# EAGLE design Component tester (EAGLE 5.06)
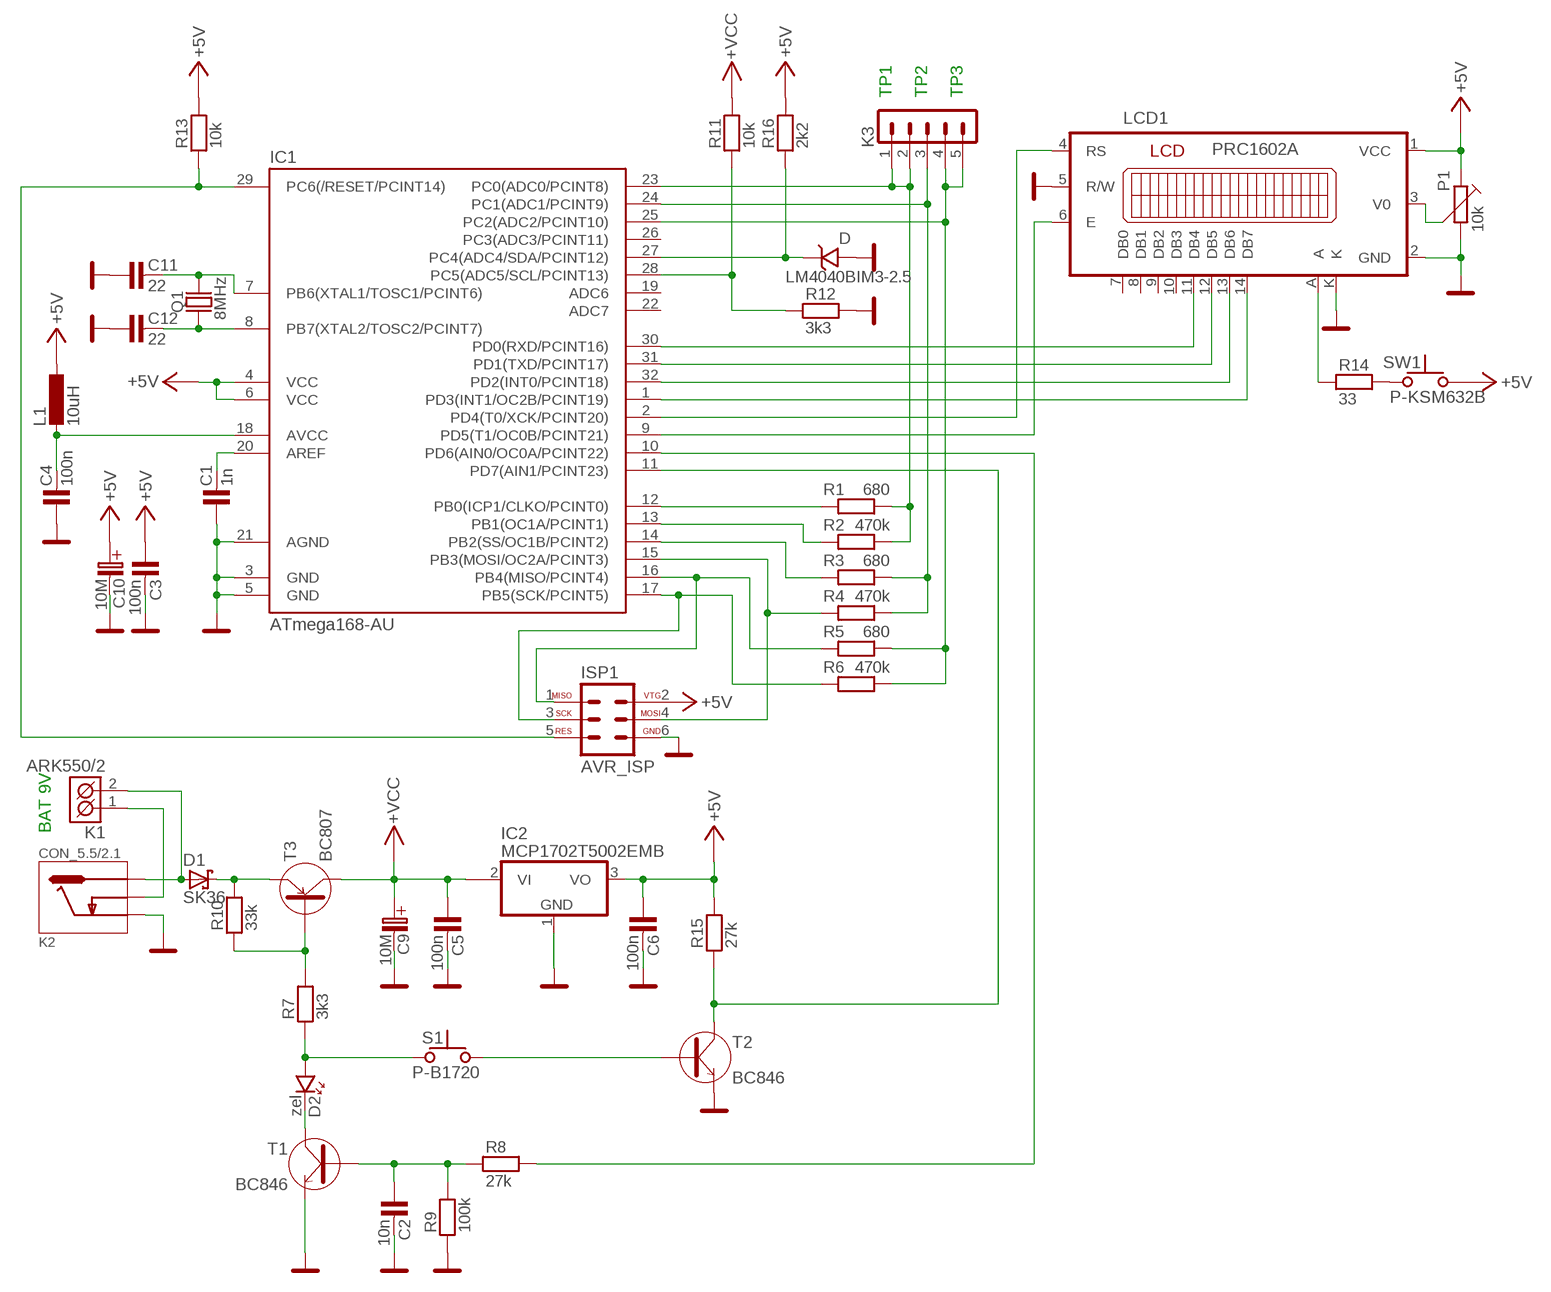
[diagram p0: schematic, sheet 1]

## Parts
C1  1n  C-KERAMIK_SMD_1206  [1206]
C2  10n  C-KERAMIK_SMD_1206  [1206]
C3  100n  C-KERAMIK_SMD_1206  [1206]
C4  100n  C-KERAMIK_SMD_1206  [1206]
C5  100n  C-KERAMIK_SMD_1206  [1206]
C6  100n  C-KERAMIK_SMD_1206  [1206]
C9  10M  10M/35V_SMD  [C_EL-SMD_C]
C10  10M  10M/35V_SMD  [C_EL-SMD_C]
C11  22  C-KERAMIK_SMD_1206  [1206]
C12  22  C-KERAMIK_SMD_1206  [1206]
D  LM4040BIM3-2.5  LM4040_SOT23  [SOT-23]
D1  SK36  SCHOTTKY-DIODESMC  [SMC]
D2  zel  LED_5  [LED_5]
IC1  ATmega168-AU  ATMEGA48/88/168-AU  [TQFP32-08]
IC2  MCP1702T5002EMB  MCP170312MB  [SOT89]
ISP1  AVR_ISP  [MLW06G]
K1  ARK550/2  [ARK550/2]
K2  CON_5.5/2.1  CON_PWR_5.5/2.1  [CON_PWR_5.5/2.1]
K3  PSH02-05P  [PSH02-05P]
L1  10uH  L-EU0207/10  [0207/10]
LCD1  PRC1602A  [PRC1602A]
P1  10k  TRIMRPT6V  [PT6V]
Q1  8MHz  XTAL_HC-49U  [HC-49U]
R1  680  R_SMD_1206  [1206]
R2  470k  R_SMD_1206  [1206]
R3  680  R_SMD_1206  [1206]
R4  470k  R_SMD_1206  [1206]
R5  680  R_SMD_1206  [1206]
R6  470k  R_SMD_1206  [1206]
R7  3k3  R_SMD_1206  [1206]
R8  27k  R_SMD_1206  [1206]
R9  100k  R_SMD_1206  [1206]
R10  33k  R_SMD_1206  [1206]
R11  10k  R_SMD_1206  [1206]
R12  3k3  R_SMD_1206  [1206]
R13  10k  R_7,5  [R-7,5]
R14  33  R_SMD_1206  [1206]
R15  27k  R_SMD_1206  [1206]
R16  2k2  R_SMD_1206  [1206]
S1  P-B1720  [P-B1720]
SW1  P-KSM632B  [P-KSM632B]
T1  BC846  [SOT-23]
T2  BC846  [SOT-23]
T3  BC807  [SOT-23]

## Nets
+5V: C3.1 C6.1 C10.+(C_EL+) IC1.4(VCC) IC1.6(VCC) IC2.3(VO) ISP1.2 L1.1 LCD1.1(VCC) P1.1 R13.2 R15.2 R16.2 SW1.1
GND: C1.1 C2.2 C3.2 C4.1 C5.2 C6.2 C9.-(C_EL-) C10.-(C_EL-) C11.1 C12.1 D.2(A) IC1.3(GND) IC1.5(GND) IC1.21(AGND) IC2.1(GND) ISP1.6 K2.3 LCD1.2(GND) LCD1.5(R/W) LCD1.K P1.2 R9.1 R12.2 T1.2(E) T2.2(E)
N$1: IC1.30(PD0(RXD/PCINT16)) LCD1.11(DB4)
N$2: IC1.31(PD1(TXD/PCINT17)) LCD1.12(DB5)
N$3: IC1.32(PD2(INT0/PCINT18)) LCD1.13(DB6)
N$4: IC1.1(PD3(INT1/OC2B/PCINT19)) LCD1.14(DB7)
N$5: IC1.9(PD5(T1/OC0B/PCINT21)) LCD1.6(E)
N$6: LCD1.3(V0) P1.3
N$7: LCD1.A R14.1
N$8: IC1.2(PD4(T0/XCK/PCINT20)) LCD1.4(RS)
N$9: IC1.16(PB4(MISO/PCINT4)) ISP1.1 R5.1
N$10: IC1.17(PB5(SCK/PCINT5)) ISP1.3 R6.1
N$11: R14.2 SW1.2
N$12: D1.C R10.2 T3.2(E)
N$13: D.1(K) IC1.27(PC4(ADC4/SDA/PCINT12)) R16.1
N$14: IC1.28(PC5(ADC5/SCL/PCINT13)) R11.1 R12.1
N$15: C12.2 IC1.8(PB7(XTAL2/TOSC2/PCINT7)) Q1.1
N$16: C11.2 IC1.7(PB6(XTAL1/TOSC1/PCINT6)) Q1.2
N$17: IC1.23(PC0(ADC0/PCINT8)) K3.1 K3.2 R1.2 R2.2
N$18: IC1.24(PC1(ADC1/PCINT9)) K3.3 R3.2 R4.2
N$19: C1.2 IC1.20(AREF)
N$20: IC1.25(PC2(ADC2/PCINT10)) K3.4 K3.5 R5.2 R6.2
N$21: IC1.12(PB0(ICP1/CLKO/PCINT0)) R1.1
N$22: IC1.13(PB1(OC1A/PCINT1)) R2.1
N$23: IC1.14(PB2(SS/OC1B/PCINT2)) R3.1
N$24: IC1.15(PB3(MOSI/OC2A/PCINT3)) ISP1.4 R4.1
N$25: R7.2 R10.1 T3.1(B)
N$26: D2.A R7.1 S1.2
N$28: D2.K T1.3(C)
N$29: S1.1 T2.1(B)
N$30: IC1.11(PD7(AIN1/PCINT23)) R15.1 T2.3(C)
N$31: IC1.10(PD6(AIN0/OC0A/PCINT22)) R8.2
N$32: C2.1 R8.1 R9.2 T1.1(B)
N$33: D1.A K1.2(K2) K2.1
N$34: K1.1(K1) K2.2
N$35: C4.2 IC1.18(AVCC) L1.2
RES: IC1.29(PC6(/RESET/PCINT14)) ISP1.5 R13.1
VCC: C5.1 C9.+(C_EL+) IC2.2@1(VI1) R11.2 T3.3(C) ; supply symbol labelled +VCC
Unconnected: IC1.19(ADC6) IC1.22(ADC7) IC1.26(PC3(ADC3/PCINT11)) IC2.2(VI) LCD1.7(DB0) LCD1.8(DB1) LCD1.9(DB2) LCD1.10(DB3) S1.3 S1.4

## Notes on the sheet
- TP1 | TP2 | TP3
- BAT 9V

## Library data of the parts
C1-C6 C11 C12 = #PaJa_31:C-KERAMIK: Kondenzator - keramicky
C9 C10 = #PaJa_C-el_2:10M/35V
D = #PaJa_31:LM4040: Precision Micropower Shunt Voltage Reference : 2,5V
D1 = diode:SCHOTTKY-DIODE: Schottky Diode
D2 = #PaJa_31:LED: LED - jednobarevna
IC1 = atmega8:ATMEGA48/88/168
IC2 = linear:MCP1703*: 250 mA, 16V, Low Quiescent Current LDO Regulator Source: http://ww1.microchip.com/downloads/en/DeviceDoc/22049b.pdf
ISP1 = #PaJa_31:AVR_ISP: AVR ISP konektor (dle standardu)
K1 = #PaJa_konektory:ARK550/2: Svorkovnice - roztec 3,5mm - dvojita
K2 = #PaJa_konektory:CON_PWR_5.5/2.1: Napájecí konektor - do DPS s prepinacem 5.5 / 2.1mm
K3 = #PaJa_konektory:PSH02-05: Konektory se zamkem - vidlice - 5pin
L1 = resistor:L-EU: INDUCTOR, European symbol
LCD1 = #PaJa_displeje:PRC1602A: LCD - 2x16 + LED (TME - LCM1602ASL) LCD Anzeige TC1602E(L) http://www.lcd-module.de/deu/pdf/doma/dip162-d.pdf
P1 = #PaJa_31:TRIMR: Trimr
Q1 = #PaJa_31:XTAL_HC-49U: Krystal - 1MHz - 48MHz
R1-R16 = #PaJa_31:R: Rezistor
S1 = #PaJa_prepinace:P-B1720: &micro;-tlacitko
SW1 = #PaJa_prepinace:P-KSM632B: &micro;-tlacitko
T1 T2 = #PaJa_31:BC846: SMD tranzistor - NPN - ekv. BC546
T3 = #PaJa_31:BC807: SMD tranzistor - PNP - ekv. BC327

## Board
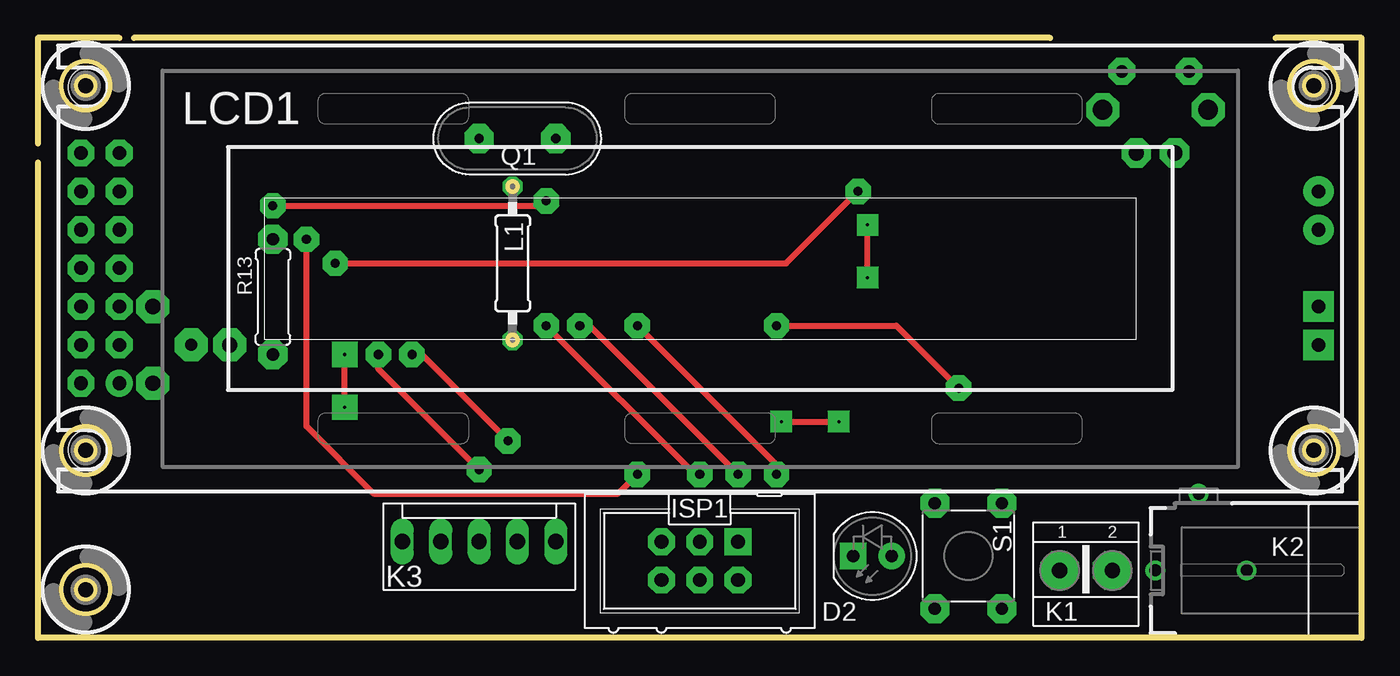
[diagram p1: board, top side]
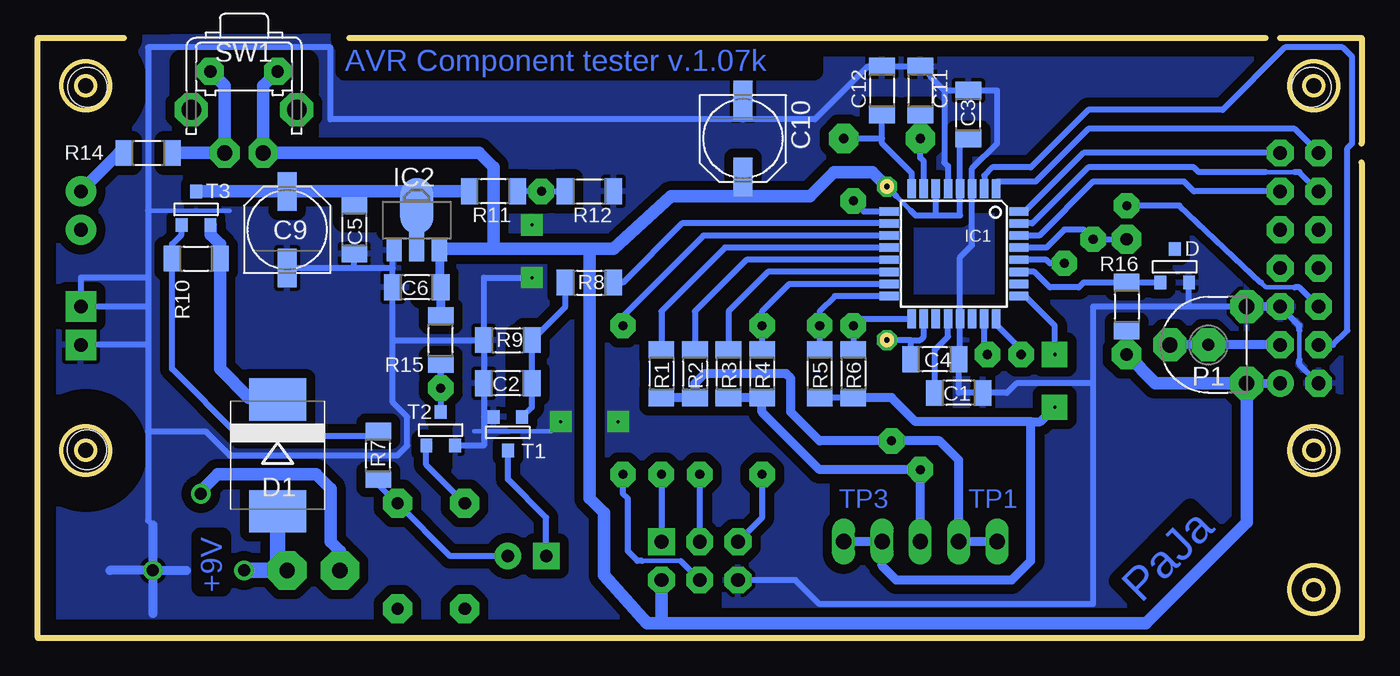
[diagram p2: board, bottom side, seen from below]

Size 87.63 x 39.7 mm. Coordinates in mm from the lower left corner, seen from the top.
Outline: 87.62,39.69 87.62,0 0,0
Outline: 87.63,39.7 81.92,39.7
Outline: 66.99,39.7 6.35,39.7
Outline: 5.4,39.7 0,39.7 0,32.71
Outline: 0,31.44 0,0.01
Outline: circle at 31.43,19.7 radius 0.32
Outline: circle at 31.43,29.86 radius 0.32
Copper layers (1*16): Top 0.035mm / dielectric 1.5mm / Bottom 0.035mm
Design rules "default": minimum track width 10mil, minimum drill 24mil, track to track 8mil, track to pad 8mil, pad to pad 8mil, via to via 8mil, smd to smd 8mil, copper to edge 40mil, drill to drill 8mil, minimum pad ring 10mil, minimum via ring 8mil, stop-mask expansion 4mil, vias tented up to drill 0mil, thermal gap 10mil
bRestrict: 15 lines

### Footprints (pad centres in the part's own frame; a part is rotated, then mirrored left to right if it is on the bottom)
1206 = smd 1.143 x 1.702: 1 -1.587,0; 2 1.587,0
C_EL-SMD_C = smd 2.54 x 1.27: + 2.54,0; - -2.54,0
SOT-23 = smd 0.787 x 0.889: 1 -0.953,-0.953; 2 0.953,-0.953; 3 0,1.27
SMC = smd 2.8 x 3.8: A 3.7,0; C -3.7,0
LED_5 = drill 0.813 pad 1.778 round: A -1.27,0 | drill 0.813 pad 1.778 square: K 1.27,0
TQFP32-08 = smd 1.27 x 0.559: 1 -4.293,2.8; 2 -4.293,2; 3 -4.293,1.2; 4 -4.293,0.4; 5 -4.293,-0.4; 6 -4.293,-1.2; 7 -4.293,-2; 8 -4.293,-2.8; 17 4.293,-2.8; 18 4.293,-2; 19 4.293,-1.2; 20 4.293,-0.4; 21 4.293,0.4; 22 4.293,1.2; 23 4.293,2; 24 4.293,2.8 | smd 0.559 x 1.27: 9 -2.8,-4.293; 10 -2,-4.293; 11 -1.2,-4.293; 12 -0.4,-4.293; 13 0.4,-4.293; 14 1.2,-4.293; 15 2,-4.293; 16 2.8,-4.293; 25 2.8,4.293; 26 2,4.293; 27 1.2,4.293; 28 0.4,4.293; 29 -0.4,4.293; 30 -1.2,4.293; 31 -2,4.293; 32 -2.8,4.293
SOT89 = smd 1 x 1.5: 1 -1.499,-1.981; 3 1.499,-1.981 | smd 1 x 2: 2 0,-1.727 | smd 2.2 x 3.7: 2@1 0,0.94
MLW06G = drill 0.914 pad 1.778 square: 1 -2.54,-1.27 | drill 0.914 pad 1.778 octagon: 2 -2.54,1.27; 3 0,-1.27; 4 0,1.27; 5 2.54,-1.27; 6 2.54,1.27
ARK550/2 = drill 1.016 pad 2.54 octagon: 1 0,0; 2 3.493,0
CON_PWR_5.5/2.1 = drill 0.8 pad 1.27 round: 1 6.032,0; 2 3.175,-5.08; 3 0,0
PSH02-05P = drill 1.016 pad 1.422 long: 1 -5.08,0; 2 -2.54,0; 3 0,0; 4 2.54,0; 5 5.08,0
0207/10 = drill 0.813 octagon: 1 -5.08,0; 2 5.08,0
PRC1602A = drill 0.9 pad 1.778 round: 1 -38.417,-7.62 | drill 0.9 pad 1.778 octagon: 2 -40.958,-7.62; 3 -38.417,-5.08; 4 -40.958,-5.08; 5 -38.417,-2.54; 6 -40.958,-2.54; 7 -38.417,0; 8 -40.958,0; 9 -38.417,2.54; 10 -40.958,2.54; 11 -38.417,5.08; 12 -40.958,5.08; 13 -38.417,7.62; 14 -40.958,7.62 | drill 0.9 pad 2 round: A 40.958,5.08; A1 40.958,2.54; A2 40.958,2.54 | drill 0.9 pad 2 square: K 40.958,-5.08; K1 40.958,-2.54; K2 40.958,-2.54 | hole 2.6: -40.49,11.976; -40.49,-12.026; 40.553,-12.026; 40.522,11.976
PT6V = drill 1.016 pad 2.184 octagon: 1 -2.54,-2.54; 2 2.54,-2.54; 3 0,2.54
HC-49U = drill 0.61 pad 1.93 octagon: 1 -2.54,0; 2 2.54,0
R-7,5 = drill 0.813 pad 1.93 octagon: 1 -3.81,0; 2 3.81,0
P-B1720 = drill 0.813 pad 1.93 octagon: 1 -3.493,-2.223; 2 -3.493,2.223; 3 3.493,-2.223; 4 3.493,2.223
P-KSM632B = drill 0.813 pad 1.778 octagon: 1 -2.223,0; 2 2.223,0 | drill 1.3 pad 2.184 octagon: A -3.493,2.54; B 3.493,2.54
HOLE_3,0 = hole 3.2: 0,0

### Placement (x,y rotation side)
C1  26.67,16.2 180 bottom
C2  56.52,16.84 180 bottom
C3  26.04,34.62 90 bottom
C4  28.26,18.43 180 bottom
C5  66.67,27 270 bottom
C6  62.55,23.19 180 bottom
C9  71.12,27 90 bottom
C10  40.96,33.03 270 bottom
C11  29.21,36.2 270 bottom
C12  31.75,36.2 270 bottom
D  12.38,24.46 0 bottom
D1  71.75,12.07 270 bottom
D2  55.24,5.41 180 top
IC1  26.99,25.41 270 bottom
IC2  62.55,27.63 0 bottom
ISP1  43.81,5.09 180 top
K1  67.63,4.46 0 top
K2  80.01,4.46 180 top
K3  29.21,6.36 0 top
L1  31.43,24.78 270 top
LCD1  43.81,24.46 0 top
P1  10.16,19.38 90 bottom
Q1  31.75,33.03 180 top
R1  46.35,17.47 270 bottom
R2  44.13,17.47 270 bottom
R3  41.91,17.47 270 bottom
R4  39.69,17.47 270 bottom
R5  35.88,17.47 270 bottom
R6  33.66,17.47 270 bottom
R7  65.09,12.07 90 bottom
R8  51.12,23.51 0 bottom
R9  56.52,19.7 0 bottom
R10  77.15,25.09 0 bottom
R11  57.47,29.54 180 bottom
R12  51.12,29.54 0 bottom
R13  15.56,22.55 270 top
R14  80.33,32.08 0 bottom
R15  60.96,19.7 90 bottom
R16  15.56,21.92 270 bottom
S1  61.59,5.41 270 top
SW1  73.98,37.48 180 bottom
T1  56.52,13.66 180 bottom
T2  60.96,13.66 0 bottom
T3  77.15,28.27 0 bottom
U$1  [HOLE_3,0]  3.17,3.18 0 top
U$2  [HOLE_3,0]  3.17,12.39 0 top
U$3  [HOLE_3,0]  84.45,12.39 0 top
U$4  [HOLE_3,0]  84.45,36.52 0 top
U$5  [HOLE_3,0]  3.17,36.52 0 top

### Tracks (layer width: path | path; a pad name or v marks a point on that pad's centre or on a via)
+5V  (via drill 1 pad 1.93)
  Bottom 0.305: 30.8,29.22 29.84,28.27
  Bottom 0.406: 28.19,27.95 IC1.6 | 28.19,27.95 26.59,27.95 IC1.4 26.59,32.48 C3.1 | L1.1 30.8,29.22 | 29.84,28.27 29.53,27.95 28.19,27.95 | 61.05,23.28 C6.1 | 60.97,25.73 IC2.3
  Bottom 0.61: IC2.3 61.05,23.28 | C6.1 R15.2 | P1.1 LCD1.1
  Bottom 0.813: R16.2 R13.2 13.65,16.84 P1.1 7.62,7.63 14.29,0.96 46.35,0.96 | L1.1 32.38,30.81 34.92,30.81 36.51,29.22 40.96,29.22 | 57.47,25.73 57.47,31.12 58.42,32.08 v72.71,32.08 72.71,36.52 SW1.1 | 57.47,25.73 60.97,25.73 | 40.96,29.22 45.72,29.22 49.53,25.73 51.12,25.73 | 40.96,29.22 C10.+ | 51.12,25.73 57.47,25.73 | 51.12,25.73 51.12,9.22 50.16,8.27 50.16,4.14 47.31,0.96 46.35,0.96 | 46.35,0.96 ISP1.2
GND  (via drill 0.2 pad 1.42)
  Top 0.406: v49.21,14.3 v53.02,14.3 | v54.93,23.82 v54.93,27.32
  Bottom 0.305: 4.13,18.43 4.13,20.33 | 80.33,28.27 74.93,28.27 | v53.02,14.3 53.66,13.66 58.74,13.66
  Bottom 0.406: LCD1.5 4.13,20.65 4.13,20.33 | 4.13,18.43 4.13,18.11 LCD1.2 | 11.43,21.92 D.2 | ISP1.6 37.47,3.82 35.88,2.23 17.78,2.23 17.78,16.84 | 17.78,16.84 22.86,16.84 23.5,16.2 C1.1 26.67,16.2 C4.1 26.59,18.83 IC1.21 26.59,25.18 25.79,25.98 IC1.3 25.79,31.06 24.13,32.71 24.13,36.2 C3.2 27.62,36.2 | 66.67,24.46 C9.- | 66.67,24.46 C5.2 | 64.14,24.46 66.67,24.46 | 64.14,24.46 64.14,25.56 IC2.1 | 64.14,24.46 C6.2 64.14,19.7 | R9.1 C2.2 58.1,14.62 | 64.14,19.7 R9.1 | 80.33,23.82 80.33,28.27 80.33,39.06 68.26,39.06 68.26,34.3 40.96,34.3 | 84.77,22.55 84.77,23.82 80.33,23.82 | 80.33,21.92 84.14,21.92 | 80.33,23.82 80.33,21.92 | 80.33,21.92 80.33,19.38 | 80.33,19.38 LCD1.K | R9.1 58.1,23.82 v54.93,23.82 | 40.96,34.3 C10.- | 40.96,34.3 36.2,34.3 32.7,37.79 C12.1 C11.1 28.89,37.48 28.57,37.48 28.57,37.16 27.62,36.2 | P1.2 11.43,21.92 | 64.14,19.7 64.14,15.57 63.18,14.62 63.18,12.71 63.82,12.07 74.93,12.07 76.52,13.66 80.33,13.66 | IC1.5 27.39,31.21 27.62,31.44 27.62,36.2 | 80.33,19.38 80.33,13.66 | 80.33,13.66 80.33,7.77 80.01,7.45 | 17.78,16.84 17.78,21.92 11.43,21.92 | 58.1,14.62 58.1,12.71 T2.2 | 58.1,14.62 T1.2
  Bottom 0.61: LCD1.5 P1.2 | 80.01,7.45 K2.3 | K2.3 77.79,4.46 | K2.3 82.87,4.46 | K2.3 80.01,1.6
  pour Bottom (isolate 0.61): 0,0.01 0,40.02 87.63,39.7 87.63,0.01
N$1
  Bottom 0.406: IC1.30 21.34,26.61 17.78,30.17 11.75,30.17 11.11,29.54 LCD1.11
N$2
  Bottom 0.305: 4.45,30.81 6.35,30.81
  Bottom 0.406: LCD1.12 4.13,30.81 4.45,30.81 | IC1.31 21.81,27.41 18.1,31.12 11.11,31.12 10.79,30.81 6.35,30.81
N$3
  Bottom 0.406: IC1.32 22.28,28.21 18.41,32.08 LCD1.13
N$4
  Bottom 0.406: LCD1.14 4.45,33.66 18.1,33.66 21.59,30.17 24.13,30.17 24.13,29.76 IC1.1
N$5  (via drill 0.6 pad 1.68)
  Top 0.406: v15.56,28.59 33.34,28.59 v33.66,28.9
  Bottom 0.305: 4.45,23.19 6.35,23.19 6.67,23.51
  Bottom 0.406: LCD1.6 4.13,23.19 4.45,23.19 | IC1.9 32.96,28.21 v33.66,28.9 | 6.67,23.51 12.06,28.59 v15.56,28.59
N$6  (via drill 0.8 pad 2.18)
  Bottom 0.61: LCD1.3 v10.16,19.38 P1.3
N$7
  Bottom 0.813: R14.1 82.23,32.08 LCD1.A
N$8
  Bottom 0.406: LCD1.4 1.91,19.38 0.95,20.33 0.95,32.39 0.64,32.71 0.64,38.43 1.27,39.06 5.08,39.06 9.21,34.93 18.1,34.93 21.91,31.12 24.45,31.12 24.99,30.59 IC1.2
N$9  (via drill 0.6 pad 1.68)
  Top 0.406: v35.88,20.65 36.51,20.65 v46.35,10.8
  Bottom 0.406: R5.1 v35.88,20.65 35.88,21.6 34.87,22.61 IC1.16 | v46.35,10.8 ISP1.1
N$10  (via drill 0.6 pad 1.68)
  Top 0.406: v33.66,20.65 43.5,10.8 v43.81,10.8
  Bottom 0.406: 33.34,19.06 R6.1 v33.66,20.65 33.19,21.12 IC1.17 | ISP1.3 v43.81,10.8
N$11  (via drill 1 pad 1.93)
  Bottom 0.813: R14.2 v75.25,32.08 75.25,36.52 SW1.2
N$12
  Bottom 0.61: R10.2 75.56,26.05
  Bottom 0.813: D1.C 73.66,15.88 75.56,17.79 R10.2 | 75.56,26.05 76.2,26.68 T3.2
N$13
  Bottom 0.406: IC1.27 21.66,24.21 20.64,23.19 18.73,23.19 18.41,23.51 R16.1 D.1
N$14  (via drill 0.6 pad 1.68)
  Top 0.406: v19.68,24.78 49.53,24.78 v54.29,29.54
  Bottom 0.406: v19.68,24.78 20.64,24.78 20.87,25.01 IC1.28 | R11.1 v54.29,29.54 R12.1
N$15
  Bottom 0.406: 31.75,33.03 C12.2 | 31.75,33.03 Q1.1 | 31.75,33.03 31.75,32.71 29.79,30.75 IC1.8
N$16
  Bottom 0.406: IC1.7 28.99,31.54 29.21,31.76 Q1.2 C11.2
N$17  (via drill 0.6 pad 1.68)
  Top 0.406: v24.77,18.74 25.4,18.74 v31.11,13.03
  Bottom 0.406: v24.77,18.74 24.99,18.96 IC1.23
  Bottom 0.61: R1.2 R2.2 44.13,16.84 43.5,17.47 38.1,17.47 37.78,17.16 37.78,14.93 35.88,13.03 v31.11,13.03 27.94,13.03 26.67,11.76 K3.2 K3.1
N$18  (via drill 0.6 pad 1.68)
  Top 0.406: v22.54,18.74 22.54,17.79 v29.21,11.12
  Bottom 0.406: v22.54,18.74 22.54,19.06 24.13,20.65 24.13,21.06 IC1.24
  Bottom 0.61: R3.2 R4.2 39.69,14.93 35.88,11.12 v29.21,11.12 K3.3
N$19
  Bottom 0.406: C1.2 28.26,19.06 27.39,19.93 IC1.20
N$20  (via drill 0.2 pad 1.68)
  Top 0.406: v20.32,18.74 v20.32,15.25 20.32,15.57
  Bottom 0.406: R5.2 R6.2 33.34,15.88 | v20.32,18.74 20.32,20.65 22.23,22.55 22.64,22.55 IC1.25
  Bottom 0.61: K3.5 K3.4 31.75,4.77 30.8,3.82 23.18,3.82 21.91,5.09 21.91,14.3 | 21.91,14.3 29.53,14.3 31.11,15.88 R6.2 | 21.91,14.3 21.27,14.3 v20.32,15.25
N$21
  Bottom 0.406: IC1.12 39.37,25.81 | 39.37,25.81 39.92,25.81 | R1.1 46.35,21.6 42.15,25.81 39.37,25.81
N$22
  Bottom 0.406: R2.1 44.13,21.6 40.72,25.01 IC1.13
N$23
  Bottom 0.406: R3.1 41.91,21.6 39.3,24.21 IC1.14
N$24  (via drill 0.6 pad 1.68)
  Top 0.406: v39.69,20.65 48.9,11.44 v48.9,10.8
  Bottom 0.305: 45.09,5.09 47.62,5.09
  Bottom 0.406: IC1.15 37.88,23.41 39.69,21.6 v39.69,20.65 R4.1 | ISP1.4 45.09,5.09 | 47.62,5.09 47.94,5.09 48.58,5.72 48.58,9.22 48.9,9.54 v48.9,10.8
N$25
  Bottom 0.406: T3.1 78.11,26.68 78.74,26.05 R10.1 78.74,17.79 74.3,13.35 65.09,13.35 R7.2
N$26
  Bottom 0.406: D2.A 60.33,5.41 S1.2 65.09,10.17 R7.1
N$28
  Bottom 0.406: D2.K 53.98,7.95 56.52,10.49 T1.3
N$29
  Bottom 0.406: T2.1 61.91,11.44 S1.1
N$30  (via drill 0.6 pad 1.68)
  Top 0.406: v60.96,16.52 56.83,20.65 v48.9,20.65
  Bottom 0.406: T2.3 R15.1 v60.96,16.52 | IC1.11 43.57,26.61 48.9,21.28 v48.9,20.65
N$31
  Bottom 0.406: IC1.10 44.99,27.41 48.9,23.51 R8.2
N$32
  Bottom 0.406: T1.1 54.93,15.25 C2.1 R9.2 52.7,21.92 R8.1
N$33
  Bottom 1.016: K1.2 71.75,4.46 | 71.75,4.46 D1.A | 71.75,4.46 K2.1
N$34
  Bottom 0.813: K1.1 67.63,5.72 68.26,6.36 68.26,9.85 69.22,10.8 75.72,10.8 76.83,9.69 K2.2
N$35
  Bottom 0.406: 29.84,19.7 L1.2 | C4.2 29.84,19.7 | 29.84,19.7 29.21,19.7 28.99,19.92 IC1.18
RES  (via drill 0.6 pad 1.68)
  Top 0.406: v39.69,10.8 38.42,9.54 22.23,9.54 17.78,13.98 v17.78,26.36
  Bottom 0.406: IC1.29 20.87,25.81 19.68,27 18.41,27 v17.78,26.36 R13.1 | ISP1.5 39.69,7.95 v39.69,10.8
VCC
  Bottom 0.406: 62.55,29.22 IC2.2@1 | 62.55,29.22 62.55,29.54 | 62.23,29.54 62.55,29.22
  Bottom 0.61: 66.67,29.54 C5.1
  Bottom 0.813: T3.3 C9.+ 66.67,29.54 62.55,29.54 | R11.2 62.23,29.54

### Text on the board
Bottom: AVR Component tester v.1.07k | TP1 | TP3 | +9V | PaJa
wago-cervena: 0R | 0R | 0R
